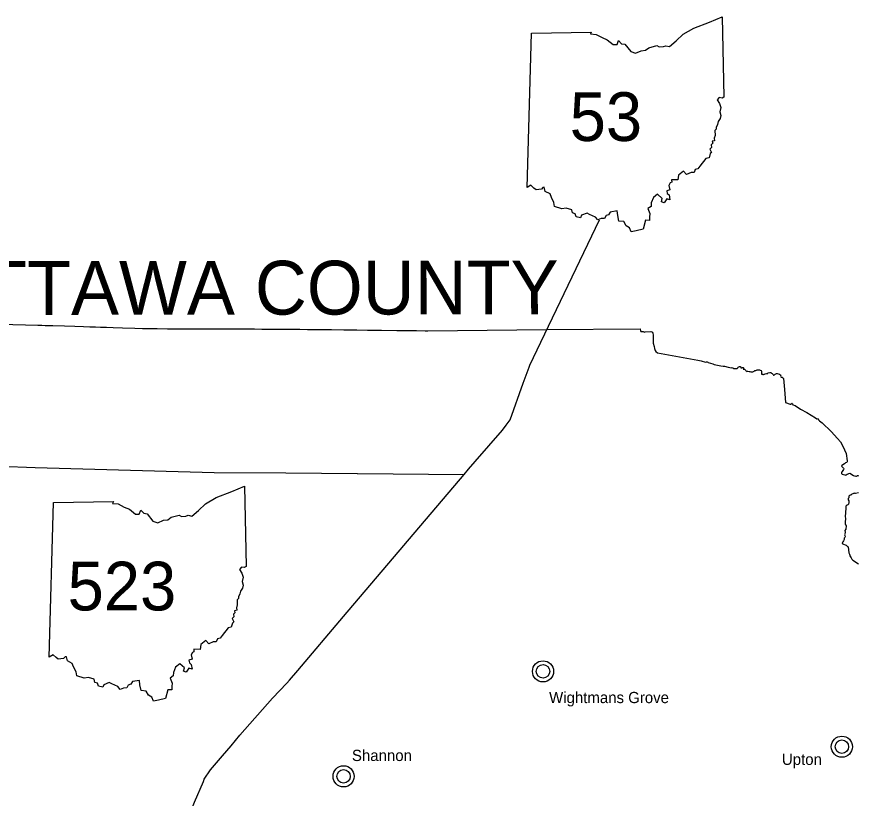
# Model space of a CAD drawing. Extents: x 0 to 798, y 0 to 440.
# Drawn here: x 368.1 to 446.4, y 267.4 to 340 of the extents above; entities that cross this region are included whole.
import ezdxf

# ---------------------------------------------------------------- set-up
doc = ezdxf.new("R2010")
doc.units = 0
for name, color, linetype in [('DV_X_Corp_Line', 7, 'Continuous'), ('GM_X_Adjacent_County_Text', 7, 'Continuous'), ('GM_X_County', 7, 'Continuous'), ('GM_X_State_Route', 7, 'Continuous'), ('PV_P_Text', 7, 'Continuous')]:
    doc.layers.add(name, color=color, linetype=linetype)

msp = doc.modelspace()

# ---------------------------------------------------------------- linework, layer by layer
at = {"layer": 'DV_X_Corp_Line'}
for centre, radius in [((417.069, 279.189), 0.982), ((417.069, 279.189), 0.623), ((444.855, 272.189), 0.982), ((444.855, 272.189), 0.623), ((398.525, 269.434), 0.982), ((398.525, 269.434), 0.623)]:
    msp.add_circle(centre, radius, dxfattribs=at)
at = {"layer": 'GM_X_County'}
for points in [[(366.645, 311.454), (370.089, 311.366), (370.129, 311.367), (370.206, 311.365), (370.478, 311.351), (370.783, 311.341), (371.48, 311.322), (372.593, 311.29), (373.533, 311.266), (374.354, 311.234), (374.938, 311.215), (375.029, 311.212), (375.124, 311.209), (375.18, 311.204), (375.228, 311.203), (375.324, 311.2), (375.452, 311.193), (375.914, 311.179), (376.488, 311.162), (377.104, 311.145), (377.963, 311.115), (379.11, 311.077), (379.837, 311.055), (379.953, 311.048), (380.09, 311.047), (380.713, 311.036), (381.205, 311.035), (382.168, 311.03), (382.969, 311.025), (384.858, 311.013), (385.718, 311.01), (386.414, 311.008), (386.591, 311.007), (386.875, 311.01), (387.43, 311.007), (387.952, 311.009), (388.304, 311.005), (389.046, 311.005), (389.582, 311.002), (390.234, 311.003), (390.935, 310.996), (391.694, 310.992), (392.289, 310.991), (393.245, 310.992), (393.519, 310.99), (394.472, 310.973), (395.167, 310.967), (395.641, 310.961), (396.479, 310.956), (397.418, 310.941), (398.565, 310.929), (399.347, 310.923), (399.756, 310.916), (400.743, 310.907), (401.314, 310.9), (402.055, 310.891), (403.492, 310.871), (404.189, 310.865), (404.721, 310.859), (405.298, 310.852), (406.117, 310.845), (406.238, 310.845), (406.353, 310.843), (417.401, 310.963), (426.09, 311.005), (426.144, 310.827), (426.172, 310.783), (426.253, 310.766), (426.303, 310.755), (426.384, 310.755), (426.443, 310.727), (426.51, 310.721), (426.557, 310.753), (427.08, 310.777), (427.175, 310.752), (427.234, 310.706), (427.273, 310.607), (427.315, 310.444), (427.32, 310.131), (427.32, 309.687), (427.399, 309.368), (427.446, 309.175), (427.485, 309.013), (427.564, 308.91), (427.703, 308.778), (431.474, 308.102), (431.768, 308.046), (432.19, 307.934), (432.263, 307.94), (432.327, 307.948), (432.386, 307.915), (432.43, 307.887), (432.864, 307.755), (432.967, 307.699), (433.593, 307.588), (433.82, 307.548), (433.948, 307.546), (434.275, 307.445), (434.583, 307.383), (434.661, 307.423), (434.731, 307.395), (434.807, 307.344), (434.946, 307.33), (435.025, 307.342), (435.12, 307.33), (435.187, 307.392), (435.217, 307.462), (435.268, 307.501), (435.329, 307.526), (435.402, 307.523), (435.43, 307.487), (435.489, 307.442), (435.463, 307.411), (435.447, 307.389), (435.48, 307.378), (435.545, 307.406), (435.623, 307.423), (435.665, 307.439), (435.707, 307.395), (435.701, 307.316), (435.69, 307.269), (435.709, 307.258), (435.76, 307.26), (435.807, 307.263), (435.866, 307.216), (435.914, 307.143), (435.927, 307.107), (435.978, 307.104), (436.028, 307.051), (436.112, 307.068), (436.221, 307.051), (436.285, 307.04), (436.4, 307.028), (436.487, 307.028), (436.584, 307.026), (436.652, 307.065), (436.699, 307.082), (436.774, 307.137), (436.842, 307.149), (436.909, 307.171), (436.928, 307.182), (436.99, 307.199), (437.116, 307.199), (437.18, 307.193), (437.255, 307.191), (437.346, 307.143), (437.389, 307.079), (437.386, 306.982), (437.366, 306.858), (437.379, 306.818), (437.413, 306.798), (437.459, 306.815), (437.53, 306.812), (437.503, 306.775), (437.546, 306.775), (437.58, 306.761), (437.653, 306.818), (437.737, 306.848), (437.841, 306.858), (437.897, 306.832), (437.958, 306.895), (438.011, 306.919), (438.148, 306.945), (438.279, 306.945), (438.325, 306.902), (438.366, 306.882), (438.396, 306.828), (438.466, 306.788), (438.483, 306.725), (438.513, 306.705), (438.539, 306.745), (438.58, 306.755), (438.64, 306.802), (438.763, 306.855), (438.844, 306.862), (439.058, 306.815), (439.141, 306.758), (439.175, 306.671), (439.158, 306.614), (439.165, 306.561), (439.195, 306.527), (439.255, 306.524), (439.315, 306.527), (439.332, 306.507), (439.332, 306.467), (439.382, 306.44), (439.432, 306.397), (439.514, 305.374), (439.616, 304.17), (440.044, 304.007), (440.124, 304.017), (440.158, 304.087), (440.211, 304.107), (440.265, 304.047), (440.285, 303.943), (440.499, 303.9), (441.017, 303.555), (441.595, 303.238), (442.388, 302.736), (442.537, 302.659), (442.593, 302.676), (442.669, 302.564), (442.774, 302.478), (443.028, 302.273), (443.873, 301.469), (444.443, 300.839), (444.724, 300.505), (444.872, 300.251), (445.106, 299.783), (445.245, 299.427), (445.344, 298.75), (445.341, 298.661), (445.301, 298.605), (445.199, 298.552), (445.102, 298.485), (444.862, 298.318), (444.805, 298.266), (444.991, 298.073), (445.022, 298.003), (445.011, 297.937), (444.934, 297.864), (444.906, 297.826), (444.906, 297.805), (444.916, 297.774), (444.86, 297.728), (444.816, 297.646), (444.823, 297.586), (444.867, 297.517), (444.996, 297.486), (445.117, 297.45), (445.184, 297.432), (445.241, 297.439), (445.351, 297.517), (445.596, 297.597), (445.921, 297.393), (446.075, 297.338), (446.181, 297.355), (446.206, 297.329), (446.253, 297.329), (446.266, 297.375), (446.289, 297.385), (446.351, 297.383), (446.4, 297.373)], [(446.389, 295.784), (446.106, 295.719), (446.055, 295.727), (445.995, 295.745), (445.944, 295.727), (445.869, 295.681), (445.771, 295.647), (445.72, 295.603), (445.676, 295.565), (445.632, 295.562), (445.578, 295.518), (445.529, 295.487), (445.498, 295.475), (445.488, 295.41), (445.503, 295.353), (445.501, 295.302), (445.462, 295.287), (445.431, 295.261), (445.442, 295.132), (445.501, 295.037), (445.514, 294.89), (445.475, 294.738), (445.413, 294.653), (445.341, 294.632), (445.303, 294.643), (445.243, 294.578), (445.223, 294.532), (445.207, 294.437), (445.199, 293.86), (445.171, 293.628), (445.153, 293.587), (445.179, 293.383), (445.184, 293.244), (445.156, 293.17), (445.174, 292.843), (445.22, 292.799), (445.259, 292.701), (445.215, 292.41), (445.133, 292.266), (445.153, 292.116), (445.12, 291.941), (445.084, 291.884), (445.122, 291.818), (445.145, 291.694), (445.13, 291.622), (445.068, 291.563), (445.063, 291.447), (445.009, 291.333), (444.955, 291.223), (444.89, 291.107), (444.893, 291.076), (444.932, 291.035), (444.996, 290.993), (445.145, 290.957), (445.251, 290.919), (445.326, 290.865), (445.39, 290.793), (445.431, 290.746), (445.501, 290.21), (445.565, 290.087), (445.586, 289.984), (445.596, 289.922), (445.671, 289.829), (445.73, 289.737), (445.774, 289.628), (445.874, 289.536), (446.384, 289.193)]]:
    msp.add_lwpolyline(points, dxfattribs=at)
at = {"layer": 'GM_X_State_Route'}
for points in [[(415.856, 307.643), (415.856, 307.644), (416.859, 309.774), (422.313, 321.148)], [(413.643, 302.075), (414.003, 302.551), (415.22, 305.962), (415.773, 307.467), (415.856, 307.643)], [(394.265, 279.269), (398.506, 284.279), (409.751, 297.489), (410.154, 297.964), (410.772, 298.696), (413.287, 301.606), (413.641, 302.073), (413.643, 302.075)], [(359.97, 298.395), (366.572, 298.251), (369.865, 298.136), (384.257, 297.719)], [(384.257, 297.719), (386.499, 297.677), (393.17, 297.622), (399.803, 297.582), (399.829, 297.58), (409.751, 297.489)], [(388.066, 272.272), (388.068, 272.275), (388.889, 273.246), (391.914, 276.707), (393.25, 278.078), (393.5, 278.365), (394.265, 279.269)], [(381.797, 261.344), (381.963, 261.627), (383.119, 263.591), (383.962, 265.231), (384.667, 267.048), (385.489, 268.962), (385.575, 269.161), (386.159, 270.051), (387.282, 271.344), (388.066, 272.272)]]:
    msp.add_lwpolyline(points, dxfattribs=at)
at = {"layer": 'PV_P_Text'}
for p, q in [((415.581, 324.135), (415.983, 338.497)), ((415.581, 324.135), (415.983, 338.497)), ((371.166, 280.513), (371.568, 294.875)), ((371.166, 280.513), (371.568, 294.875))]:
    msp.add_line(p, q, dxfattribs=at)
for points in [[(415.983, 338.497), (421.556, 338.591), (421.469, 338.417), (421.995, 338.381), (422.553, 338.074), (423.026, 337.88), (423.604, 337.424), (423.949, 337.429), (424.095, 337.803), (424.36, 337.514), (424.674, 337.462), (425.218, 336.775), (425.666, 336.626), (426.203, 336.862), (426.605, 336.9), (426.898, 337.133), (427.663, 337.333), (427.876, 337.213), (428.281, 337.237), (428.485, 337.325), (428.838, 337.247), (429.459, 337.769), (430.099, 338.385), (431.083, 338.966), (432.553, 339.516), (433.716, 340.008), (433.884, 332.555)], [(415.983, 338.497), (421.556, 338.591), (421.469, 338.417), (421.995, 338.381), (422.553, 338.074), (423.026, 337.88), (423.604, 337.424), (423.949, 337.429), (424.095, 337.803), (424.36, 337.514), (424.674, 337.462), (425.218, 336.775), (425.666, 336.626), (426.203, 336.862), (426.605, 336.9), (426.898, 337.133), (427.663, 337.333), (427.876, 337.213), (428.281, 337.237), (428.485, 337.325), (428.838, 337.247), (429.459, 337.769), (430.099, 338.385), (431.083, 338.966), (432.553, 339.516), (433.716, 340.008), (433.884, 332.555)], [(433.884, 332.555), (433.712, 332.45), (433.445, 332.5), (433.266, 332.291), (433.488, 331.942), (433.593, 331.573), (433.5, 331.167), (433.592, 330.832), (433.529, 330.552), (433.361, 330.273), (433.303, 330.007), (433.161, 329.726), (433.173, 329.57), (433.036, 329.445), (433.061, 328.979), (432.992, 328.721), (433.016, 328.498), (432.795, 328.44), (432.846, 328.255), (432.706, 328.113), (432.736, 327.868), (432.576, 327.713), (432.731, 327.4), (432.607, 327.301), (432.504, 326.92), (432.221, 326.843), (431.654, 326.147), (431.454, 325.885), (431.229, 325.819), (431.106, 325.549), (430.829, 325.548), (430.411, 325.361), (430.14, 325.683), (429.666, 325.295), (429.611, 324.847), (429.012, 324.862), (429.035, 324.635), (428.901, 324.569), (428.779, 324.343), (428.85, 323.939), (428.57, 323.837), (428.604, 323.603), (428.783, 323.459), (428.863, 323.012), (428.565, 323.103), (428.32, 322.726), (428.069, 322.814), (428.152, 323.134), (427.727, 323.518), (427.325, 323.21), (427.116, 322.719), (427.113, 322.388), (426.814, 322.188), (427.006, 321.721), (426.971, 321.4), (426.977, 321.094), (426.603, 321.105), (426.376, 320.28)], [(433.884, 332.555), (433.712, 332.45), (433.445, 332.5), (433.266, 332.291), (433.488, 331.942), (433.593, 331.573), (433.5, 331.167), (433.592, 330.832), (433.529, 330.552), (433.361, 330.273), (433.303, 330.007), (433.161, 329.726), (433.173, 329.57), (433.036, 329.445), (433.061, 328.979), (432.992, 328.721), (433.016, 328.498), (432.795, 328.44), (432.846, 328.255), (432.706, 328.113), (432.736, 327.868), (432.576, 327.713), (432.731, 327.4), (432.607, 327.301), (432.504, 326.92), (432.221, 326.843), (431.654, 326.147), (431.454, 325.885), (431.229, 325.819), (431.106, 325.549), (430.829, 325.548), (430.411, 325.361), (430.14, 325.683), (429.666, 325.295), (429.611, 324.847), (429.012, 324.862), (429.035, 324.635), (428.901, 324.569), (428.779, 324.343), (428.85, 323.939), (428.57, 323.837), (428.604, 323.603), (428.783, 323.459), (428.863, 323.012), (428.565, 323.103), (428.32, 322.726), (428.069, 322.814), (428.152, 323.134), (427.727, 323.518), (427.325, 323.21), (427.116, 322.719), (427.113, 322.388), (426.814, 322.188), (427.006, 321.721), (426.971, 321.4), (426.977, 321.094), (426.603, 321.105), (426.376, 320.28)], [(426.376, 320.28), (425.726, 320.123), (425.275, 320.028), (425.115, 320.403), (424.792, 320.6), (424.582, 320.977), (424.119, 321.029), (424.009, 321.546), (423.957, 321.967), (423.324, 321.863), (423.149, 321.606), (422.925, 321.537), (422.794, 321.278), (422.488, 321.257), (422.159, 321.135), (421.944, 321.388), (421.405, 321.643), (421.163, 321.775), (420.656, 321.571), (420.548, 321.329), (420.145, 321.435), (420.051, 321.705), (419.807, 321.786), (419.753, 322.072), (419.232, 322.225), (418.833, 322.164), (418.129, 322.394), (418.086, 322.771), (417.847, 323.229), (417.722, 323.548), (417.277, 323.791), (417.187, 324.169), (417.045, 324.158), (416.915, 324.005), (416.421, 323.934), (416.223, 324.089), (415.947, 324.353), (415.581, 324.135)], [(426.376, 320.28), (425.726, 320.123), (425.275, 320.028), (425.115, 320.403), (424.792, 320.6), (424.582, 320.977), (424.119, 321.029), (424.009, 321.546), (423.957, 321.967), (423.324, 321.863), (423.149, 321.606), (422.925, 321.537), (422.794, 321.278), (422.488, 321.257), (422.159, 321.135), (421.944, 321.388), (421.405, 321.643), (421.163, 321.775), (420.656, 321.571), (420.548, 321.329), (420.145, 321.435), (420.051, 321.705), (419.807, 321.786), (419.753, 322.072), (419.232, 322.225), (418.833, 322.164), (418.129, 322.394), (418.086, 322.771), (417.847, 323.229), (417.722, 323.548), (417.277, 323.791), (417.187, 324.169), (417.045, 324.158), (416.915, 324.005), (416.421, 323.934), (416.223, 324.089), (415.947, 324.353), (415.581, 324.135)], [(371.568, 294.875), (377.14, 294.969), (377.053, 294.795), (377.579, 294.759), (378.138, 294.452), (378.61, 294.258), (379.188, 293.802), (379.534, 293.807), (379.68, 294.181), (379.945, 293.892), (380.259, 293.841), (380.802, 293.153), (381.251, 293.004), (381.788, 293.24), (382.189, 293.279), (382.482, 293.512), (383.247, 293.711), (383.461, 293.591), (383.865, 293.615), (384.069, 293.704), (384.422, 293.625), (385.044, 294.147), (385.684, 294.763), (386.668, 295.344), (388.138, 295.894), (389.3, 296.387), (389.468, 288.933)], [(371.568, 294.875), (377.14, 294.969), (377.053, 294.795), (377.579, 294.759), (378.138, 294.452), (378.61, 294.258), (379.188, 293.802), (379.534, 293.807), (379.68, 294.181), (379.945, 293.892), (380.259, 293.841), (380.802, 293.153), (381.251, 293.004), (381.788, 293.24), (382.189, 293.279), (382.482, 293.512), (383.247, 293.711), (383.461, 293.591), (383.865, 293.615), (384.069, 293.704), (384.422, 293.625), (385.044, 294.147), (385.684, 294.763), (386.668, 295.344), (388.138, 295.894), (389.3, 296.387), (389.468, 288.933)], [(389.468, 288.933), (389.297, 288.829), (389.03, 288.878), (388.85, 288.669), (389.072, 288.32), (389.177, 287.952), (389.084, 287.545), (389.176, 287.21), (389.114, 286.93), (388.946, 286.651), (388.888, 286.385), (388.745, 286.105), (388.757, 285.948), (388.621, 285.824), (388.646, 285.357), (388.577, 285.099), (388.6, 284.876), (388.38, 284.818), (388.43, 284.634), (388.29, 284.492), (388.32, 284.247), (388.161, 284.091), (388.315, 283.778), (388.191, 283.679), (388.088, 283.298), (387.805, 283.221), (387.239, 282.526), (387.039, 282.263), (386.814, 282.197), (386.69, 281.927), (386.414, 281.926), (385.995, 281.739), (385.724, 282.061), (385.25, 281.673), (385.196, 281.226), (384.596, 281.24), (384.619, 281.014), (384.486, 280.947), (384.364, 280.721), (384.435, 280.318), (384.154, 280.215), (384.188, 279.981), (384.368, 279.838), (384.448, 279.39), (384.149, 279.481), (383.905, 279.104), (383.654, 279.193), (383.736, 279.512), (383.312, 279.896), (382.91, 279.588), (382.7, 279.097), (382.698, 278.766), (382.399, 278.566), (382.591, 278.099), (382.556, 277.778), (382.561, 277.472), (382.187, 277.483), (381.961, 276.658)], [(389.468, 288.933), (389.297, 288.829), (389.03, 288.878), (388.85, 288.669), (389.072, 288.32), (389.177, 287.952), (389.084, 287.545), (389.176, 287.21), (389.114, 286.93), (388.946, 286.651), (388.888, 286.385), (388.745, 286.105), (388.757, 285.948), (388.621, 285.824), (388.646, 285.357), (388.577, 285.099), (388.6, 284.876), (388.38, 284.818), (388.43, 284.634), (388.29, 284.492), (388.32, 284.247), (388.161, 284.091), (388.315, 283.778), (388.191, 283.679), (388.088, 283.298), (387.805, 283.221), (387.239, 282.526), (387.039, 282.263), (386.814, 282.197), (386.69, 281.927), (386.414, 281.926), (385.995, 281.739), (385.724, 282.061), (385.25, 281.673), (385.196, 281.226), (384.596, 281.24), (384.619, 281.014), (384.486, 280.947), (384.364, 280.721), (384.435, 280.318), (384.154, 280.215), (384.188, 279.981), (384.368, 279.838), (384.448, 279.39), (384.149, 279.481), (383.905, 279.104), (383.654, 279.193), (383.736, 279.512), (383.312, 279.896), (382.91, 279.588), (382.7, 279.097), (382.698, 278.766), (382.399, 278.566), (382.591, 278.099), (382.556, 277.778), (382.561, 277.472), (382.187, 277.483), (381.961, 276.658)], [(381.961, 276.658), (381.31, 276.501), (380.859, 276.406), (380.7, 276.781), (380.377, 276.978), (380.167, 277.356), (379.703, 277.407), (379.593, 277.925), (379.542, 278.345), (378.908, 278.241), (378.734, 277.984), (378.509, 277.915), (378.378, 277.656), (378.072, 277.635), (377.743, 277.513), (377.528, 277.767), (376.989, 278.022), (376.747, 278.153), (376.241, 277.949), (376.133, 277.707), (375.729, 277.814), (375.635, 278.083), (375.391, 278.164), (375.337, 278.45), (374.816, 278.603), (374.417, 278.542), (373.713, 278.772), (373.671, 279.149), (373.431, 279.607), (373.306, 279.926), (372.861, 280.169), (372.771, 280.548), (372.629, 280.536), (372.499, 280.383), (372.005, 280.312), (371.808, 280.467), (371.531, 280.731), (371.166, 280.513)], [(381.961, 276.658), (381.31, 276.501), (380.859, 276.406), (380.7, 276.781), (380.377, 276.978), (380.167, 277.356), (379.703, 277.407), (379.593, 277.925), (379.542, 278.345), (378.908, 278.241), (378.734, 277.984), (378.509, 277.915), (378.378, 277.656), (378.072, 277.635), (377.743, 277.513), (377.528, 277.767), (376.989, 278.022), (376.747, 278.153), (376.241, 277.949), (376.133, 277.707), (375.729, 277.814), (375.635, 278.083), (375.391, 278.164), (375.337, 278.45), (374.816, 278.603), (374.417, 278.542), (373.713, 278.772), (373.671, 279.149), (373.431, 279.607), (373.306, 279.926), (372.861, 280.169), (372.771, 280.548), (372.629, 280.536), (372.499, 280.383), (372.005, 280.312), (371.808, 280.467), (371.531, 280.731), (371.166, 280.513)]]:
    msp.add_lwpolyline(points, dxfattribs=at)

# ---------------------------------------------------------------- texts
at = {"layer": 'DV_X_Corp_Line'}
for s, height, p in [('Wightmans Grove', 1.04167, (417.633, 276.238)), ('Shannon', 1.0417, (399.303, 270.857)), ('Upton', 1.0417, (439.278, 270.494))]:
    msp.add_text(s, height=height, rotation=0.00001, dxfattribs=at).set_placement(p)
at = {"layer": 'GM_X_Adjacent_County_Text'}
msp.add_text('OTTAWA COUNTY', height=5, rotation=0.07101, dxfattribs=at).set_placement((359.824, 312.298))
at = {"layer": 'PV_P_Text'}
for s, p in [('53', (419.548, 328.472)), ('523', (372.868, 284.85))]:
    msp.add_text(s, height=4.5281, dxfattribs=at).set_placement(p)

doc.saveas('drawing.dxf')
